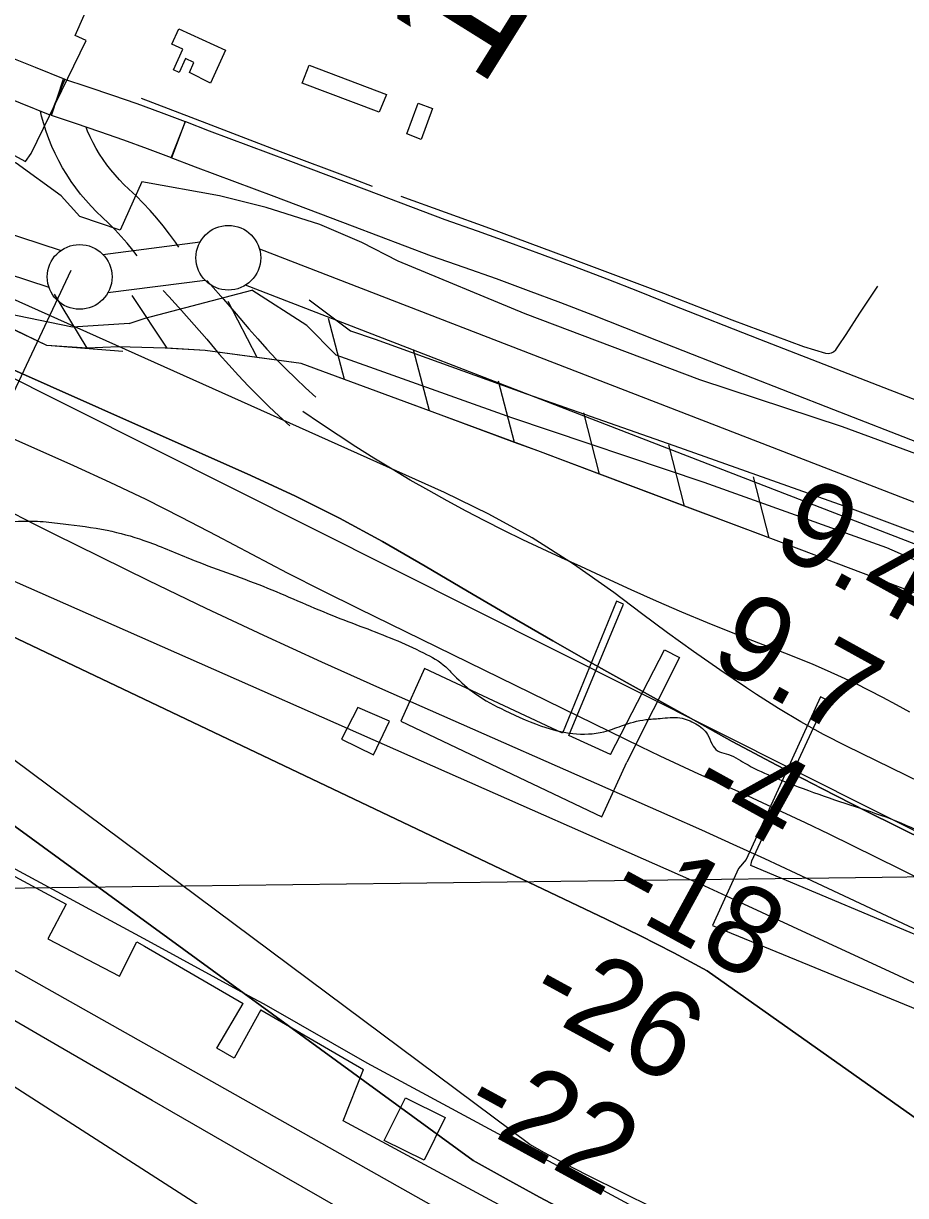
# Model space of a CAD drawing. Extents: x 3734862 to 3772949, y 391520 to 417239.
# Drawn here: x 3739114 to 3739795, y 408738 to 409644 of the extents above; entities that cross this region are included whole.
import ezdxf

# ---------------------------------------------------------------- set-up
doc = ezdxf.new("R2010")
doc.units = 0
for name, color, linetype in [('V-BLDG-OTLN', 7, 'Continuous'), ('V-CHAN-DOCK', 7, 'Continuous'), ('V-FLOD-BASE', 7, 'Continuous'), ('V-GRID-MAJR', 7, 'Continuous'), ('V-LEVE-TOET', 7, 'Continuous'), ('V-RIVR-EDGE', 7, 'Continuous'), ('V-RIVR-RANG', 7, 'Continuous'), ('V-ROAD-CNTR', 7, 'Continuous'), ('V-RRAP-FSHR', 7, 'Continuous'), ('V-SURV-IDEN', 7, 'Continuous'), ('V-SURV-LINE', 7, 'Continuous'), ('V-TOPO-DPTH', 7, 'Continuous'), ('V-TOPO-MAJR', 7, 'Continuous'), ('V-TOPO-MINR', 7, 'Continuous'), ('V-TOPO-SHOR', 7, 'Continuous'), ('V-TOPO-WATR', 7, 'Continuous'), ('V-UTIL-LINE', 7, 'Continuous')]:
    doc.layers.add(name, color=color, linetype=linetype)

msp = doc.modelspace()

# ---------------------------------------------------------------- linework, layer by layer
at = {"layer": 'V-BLDG-OTLN'}
for points in [[(3739258.67, 409597.45), (3739242.48, 409605.83), (3739245.95, 409613.61), (3739239.48, 409616.56), (3739234.59, 409605.83), (3739230.02, 409607.91), (3739237.3, 409623.91), (3739228.79, 409627.78), (3739234.13, 409639.52), (3739270.32, 409623.03)], [(3739389, 409575.07), (3739329.49, 409597.45), (3739334.75, 409611.41), (3739394.62, 409588.88)], [(3739421.27, 409554.1), (3739410.35, 409558.39), (3739419.02, 409582.11), (3739430.02, 409578.09)], [(3739439.88, 408798.78), (3739423.56, 408765.74), (3739392.84, 408780.92), (3739409.16, 408813.95)]]:
    msp.add_lwpolyline(points, close=True, dxfattribs=at)
at = {"layer": 'V-CHAN-DOCK'}
for p, q in [((3738907.07, 409092.08), (3739147.35, 408963.51)), ((3739287.71, 408892.97), (3739300, 408886.37)), ((3739297.46, 408881.72), (3739376.81, 408835.8)), ((3739300, 408886.37), (3739379.49, 408840.81))]:
    msp.add_line(p, q, dxfattribs=at)
for points in [[(3739567.46, 409078.94), (3739535.23, 409093.66), (3739577.5, 409195.17), (3739572.24, 409197.36), (3739530.35, 409095.61), (3739423.83, 409145.47), (3739405.57, 409104.69), (3739560.74, 409030.98), (3739580.19, 409073.13)], [(3739567.46, 409078.94), (3739609.14, 409159.88), (3739620.76, 409153.89), (3739580.19, 409073.13)], [(3739729.53, 409123.49), (3739672.32, 408997.98), (3739666.35, 408991.1), (3739646.26, 408947.08), (3739804.34, 408882.01), (3739826.35, 408930.09), (3739675.76, 408993.34), (3739676.75, 408996.93), (3739734.21, 409121.16), (3739729.53, 409123.49)], [(3739359.8, 409090.79), (3739384.53, 409078.73), (3739396.86, 409104.88), (3739372.49, 409115.27), (3739359.8, 409090.79)], [(3738906.99, 409099.12), (3739210.09, 408935.44), (3739287.71, 408892.97)], [(3739147.35, 408963.51), (3739133.12, 408936.63), (3739188.34, 408907.77), (3739201.91, 408934.31)], [(3739201.91, 408934.31), (3739207.84, 408931.14), (3739283.97, 408886.65)], [(3739297.46, 408881.72), (3739277.1, 408844.51), (3739263.66, 408852.27), (3739283.97, 408886.65)], [(3739379.49, 408840.81), (3739809.65, 408608.64)], [(3739786.75, 408566.78), (3739361.2, 408796.23), (3739376.81, 408835.8)]]:
    msp.add_lwpolyline(points, dxfattribs=at)
at = {"layer": 'V-FLOD-BASE'}
msp.add_lwpolyline([(3739334.78, 409430.31), (3739366.77, 409406.28), (3739385.75, 409399.78), (3739502.67, 409357.65), (3739616.51, 409317.58), (3739752.15, 409269.46), (3739870.6, 409225.01), (3739902.12, 409209.98), (3739957.18, 409174.29), (3740021.39, 409119.55), (3740101.98, 409050.62), (3740182.57, 408982.72), (3740226.59, 408950.42), (3740266.79, 408922.5), (3740306.51, 408904.34), (3740385.75, 408877.53), (3740540.11, 408823.68)], dxfattribs=at)
at = {"layer": 'V-GRID-MAJR'}
msp.add_spline([(3738908.57, 408973.48), (3741556.26, 409006.89), (3746851.64, 409074.29), (3752147, 409142.46), (3757442.36, 409211.39), (3762737.71, 409281.1), (3768033.05, 409351.58), (3770680.71, 409387.1)], degree=3, dxfattribs=at)
at = {"layer": 'V-LEVE-TOET'}
for p, q in [((3739205.63, 409521.46), (3739189.03, 409484.04)), ((3739208.3, 409416.01), (3739290.58, 409437.73)), ((3739333.09, 409410.31), (3739290.58, 409437.73)), ((3739195.96, 409411.96), (3739208.3, 409416.01))]:
    msp.add_line(p, q, dxfattribs=at)
for points in [[(3739195.96, 409411.96), (3739152.29, 409409.07), (3739100.97, 409419.58), (3739059.43, 409433.12), (3738999.95, 409455.99), (3738960.02, 409484.93), (3738928.85, 409522.56), (3738901.33, 409548.9)], [(3739189.03, 409484.04), (3739157.74, 409494.45), (3739143.43, 409510.44), (3739108.62, 409535.76), (3739085.05, 409547.68), (3739050.12, 409548.35)], [(3740557.68, 408873.85), (3740454.07, 408906.67), (3740348.44, 408946.7), (3740299.74, 408966.44), (3740256.21, 408994.88), (3740191.72, 409046.54), (3740108.31, 409115.74), (3740059.72, 409161.16), (3740022.88, 409192.14), (3739990.63, 409216.42), (3739972.71, 409228.83), (3739941.99, 409251.57), (3739902.53, 409271.27), (3739825.63, 409302.94), (3739746.66, 409332.06), (3739636.39, 409368.51), (3739501.54, 409419.46), (3739403.62, 409459.96), (3739375.43, 409474.47), (3739343.14, 409488.48), (3739301.59, 409501.51), (3739265.68, 409510.4), (3739205.63, 409521.46)], [(3739333.09, 409410.31), (3739355.59, 409387.61), (3739490.97, 409339.23), (3739639.7, 409289.26), (3739780.72, 409238.8), (3739854.02, 409206.62)]]:
    msp.add_lwpolyline(points, dxfattribs=at)
at = {"layer": 'V-RIVR-EDGE'}
msp.add_spline([(3738903.54, 409373.09), (3738918.2, 409356.83), (3738938.04, 409332.37), (3738944.77, 409313.81), (3738950.62, 409302.04), (3738968.22, 409286.63), (3738988.99, 409277.53), (3739027.4, 409264.32), (3739054.96, 409258.38), (3739073.5, 409257.43), (3739110.58, 409259.14), (3739127.31, 409259.1), (3739144.94, 409257.25), (3739178.84, 409252.19), (3739207.31, 409244.44), (3739242.54, 409230.33), (3739299.46, 409208.94), (3739352.31, 409186.65), (3739377.15, 409177.1), (3739423.22, 409157.54), (3739440.38, 409146.65), (3739446.69, 409140.3), (3739463.39, 409125.79), (3739485.96, 409113.07), (3739517.58, 409099.88), (3739538.37, 409095.31), (3739562.34, 409096.61), (3739575.91, 409101.09), (3739594.92, 409106.02), (3739605.77, 409106.9), (3739621.14, 409107.31), (3739633.34, 409102.76), (3739642.36, 409094.6), (3739645.96, 409086.9), (3739650.02, 409081.92), (3739656.8, 409079.64), (3739671.25, 409072.37), (3739691.57, 409062.37), (3739712.35, 409054.18), (3739744.42, 409042.8), (3739807.22, 409019.13), (3739846.51, 409003.21), (3739854.2, 409003.19), (3739865.5, 409002.26), (3739871.37, 408996.37), (3739884.9, 408983.22), (3739905.21, 408967.8), (3739923.73, 408960.07), (3739941.35, 408957.31), (3739946.77, 408955.03), (3739950.38, 408950.5), (3739952.16, 408939.2), (3739952.15, 408934.67), (3739958.01, 408927.88), (3739965.69, 408924.69), (3739973.83, 408924.67), (3739980.61, 408926.01), (3739993.27, 408925.53), (3740017.68, 408921.85), (3740043.89, 408913.65), (3740068.28, 408902.74), (3740089.05, 408892.74), (3740121.1, 408870.5), (3740159.47, 408846.44), (3740190.17, 408826.47), (3740216.36, 408811.94), (3740241.65, 408801.02), (3740277.78, 408783.75), (3740307.59, 408770.11), (3740323.41, 408765.55), (3740335.16, 408764.17), (3740368.15, 408757.3), (3740393, 408749.1), (3740424.16, 408733.65), (3740468.87, 408713.19), (3740503.2, 408699.55), (3740521.72, 408692.26), (3740542.48, 408676.84), (3740576.78, 408647.82), (3740600.7, 408631.48), (3740627.79, 408616.94), (3740649.04, 408613.73), (3740673.44, 408606.43), (3740710.94, 408594.58), (3740747.51, 408575.05), (3740787.23, 408546.47), (3740825.6, 408519.69), (3740852.7, 408506.51), (3740900.58, 408488.76)], degree=3, dxfattribs=at)
at = {"layer": 'V-RIVR-RANG'}
msp.add_line((3739150.96, 409452.81), (3738908.98, 408940.41), dxfattribs=at)
at = {"layer": 'V-ROAD-CNTR'}
for points in [[(3739134.86, 409572.84), (3739112.09, 409582.12), (3739089.29, 409591.12), (3739066.4, 409599.88), (3739043.35, 409608.43), (3739053.78, 409636.56), (3739076.98, 409627.96), (3739100.17, 409619.08), (3739123.26, 409609.96), (3739146.18, 409600.62)], [(3739228.6, 409539.87), (3739210.15, 409546.8), (3739191.7, 409553.51), (3739173.18, 409560.02), (3739154.59, 409566.34), (3739135.85, 409572.48), (3739145.19, 409600.99), (3739164.08, 409594.8), (3739182.98, 409588.38), (3739201.8, 409581.76), (3739220.56, 409574.94), (3739239.16, 409567.95)]]:
    msp.add_lwpolyline(points, close=True, dxfattribs=at)
for points in [[(3739202.21, 409464.07), (3739198.75, 409468.56), (3739194.38, 409473.89), (3739189.84, 409479.08), (3739185.12, 409484.14), (3739180.25, 409489.04), (3739175.03, 409493.98), (3739170.76, 409498.05), (3739166.46, 409502.47), (3739162.33, 409507.06), (3739158.39, 409511.79), (3739154.63, 409516.68), (3739151.06, 409521.72), (3739147.69, 409526.88), (3739144.52, 409532.18), (3739141.56, 409537.59), (3739138.81, 409543.11), (3739136.27, 409548.73), (3739133.95, 409554.45), (3739131.85, 409560.25), (3739129.98, 409566.14), (3739128.34, 409572.08), (3739127.45, 409575.86)], [(3739234.15, 409470.86), (3739231.58, 409474.67), (3739227.01, 409481.02), (3739222.24, 409487.23), (3739217.27, 409493.29), (3739212.1, 409499.19), (3739206.75, 409504.93), (3739201.21, 409510.52), (3739195.68, 409515.74), (3739191.86, 409519.38), (3739188.37, 409522.97), (3739185.02, 409526.69), (3739181.82, 409530.54), (3739178.77, 409534.51), (3739175.87, 409538.6), (3739173.13, 409542.79), (3739170.56, 409547.09), (3739168.15, 409551.49), (3739165.91, 409555.98), (3739163.85, 409560.54), (3739162.61, 409563.61)], [(3739808.67, 409318.5), (3739739.98, 409345.27), (3739671.61, 409371.95), (3739603.17, 409398.68), (3739578.47, 409408.65), (3739553.83, 409418.37), (3739529.11, 409427.88), (3739504.32, 409437.2), (3739479.45, 409446.31), (3739454.5, 409455.23), (3739429.23, 409464.03), (3739368.45, 409487.19), (3739307.83, 409510.04), (3739247, 409532.72), (3739228.45, 409539.92), (3739239.31, 409567.89), (3739257.67, 409560.76), (3739318.36, 409538.13), (3739379.09, 409515.24), (3739439.5, 409492.22), (3739464.48, 409483.52), (3739489.66, 409474.52), (3739514.75, 409465.33), (3739539.78, 409455.92), (3739564.72, 409446.32), (3739589.59, 409436.52), (3739614.24, 409426.56), (3739682.52, 409399.89), (3739750.87, 409373.22), (3739818.92, 409346.7)], [(3739255.85, 409445.04), (3739258.65, 409441.97), (3739268.7, 409430.68), (3739278.6, 409419.27), (3739288.19, 409407.91), (3739295.15, 409399.97), (3739302.26, 409392.16), (3739309.52, 409384.48), (3739316.93, 409376.94), (3739324.47, 409369.53), (3739332.16, 409362.26), (3739340.09, 409355.05)], [(3739222.1, 409437.38), (3739226.44, 409432.75), (3739236.37, 409421.88), (3739246.16, 409410.88), (3739255.8, 409399.76), (3739265.45, 409388.35), (3739272.77, 409379.98), (3739280.27, 409371.76), (3739287.91, 409363.67), (3739295.71, 409355.72), (3739303.66, 409347.92), (3739311.76, 409340.27), (3739319.89, 409332.87)], [(3739798.65, 409111.62), (3739788.28, 409117.43), (3739777.81, 409123.07), (3739767.25, 409128.53), (3739756.6, 409133.8), (3739745.85, 409138.89), (3739735.02, 409143.79), (3739724.11, 409148.51), (3739713.11, 409153.04), (3739702.04, 409157.38), (3739682.05, 409164.97), (3739662.15, 409172.79), (3739642.33, 409180.83), (3739622.6, 409189.1), (3739602.97, 409197.58), (3739583.43, 409206.28), (3739564, 409215.2), (3739544.66, 409224.34), (3739529.65, 409230.97), (3739514.73, 409237.8), (3739499.9, 409244.82), (3739485.16, 409252.04), (3739470.52, 409259.45), (3739455.98, 409267.06), (3739441.54, 409274.85), (3739427.2, 409282.84), (3739412.97, 409291.02), (3739398.85, 409299.38), (3739384.85, 409307.93), (3739370.95, 409316.66), (3739357.18, 409325.58), (3739343.52, 409334.68), (3739329.99, 409343.96)]]:
    msp.add_lwpolyline(points, dxfattribs=at)
at = {"layer": 'V-RRAP-FSHR'}
for p, q in [((3739163.48, 409392.85), (3739138.17, 409434.6)), ((3739225.15, 409392.82), (3739198.17, 409433.52)), ((3739294.73, 409385.64), (3739272.33, 409429.03)), ((3739362.2, 409368.65), (3739349.79, 409415.87)), ((3739427.86, 409344.38), (3739415.46, 409391.61)), ((3739493.52, 409320.12), (3739481.12, 409367.35)), ((3739559.08, 409295.58), (3739546.95, 409342.88)), ((3739624.6, 409270.93), (3739612.47, 409318.23)), ((3739690.11, 409246.28), (3739677.98, 409293.58))]:
    msp.add_line(p, q, dxfattribs=at)
for points in [[(3739190.93, 409390.28), (3739132.3, 409394.9), (3738974.21, 409471.33), (3738896.41, 409523.17)], [(3738902.29, 409472.06), (3740332.61, 408753.85), (3741222.95, 408371.28), (3742367.67, 407964.03)], [(3739163.48, 409392.85), (3739132.3, 409394.9), (3739097.42, 409411.77)], [(3739225.15, 409392.78), (3739223.71, 409392.86), (3739187.67, 409393.78), (3739163.48, 409392.85)], [(3741885.29, 408291.44), (3741623.78, 408378.23), (3741440.63, 408438.31), (3741241.33, 408499.82), (3741053.03, 408559.01), (3740880.24, 408628.55), (3740717.65, 408719.54), (3740545.64, 408780.53), (3740315.5, 408858.27), (3740127.64, 408979.39), (3739988.64, 409101.92), (3739872.92, 409177.1), (3739715.19, 409236.85), (3739511.41, 409313.52), (3739328.59, 409381.06), (3739254.6, 409391.06), (3739223.71, 409392.86)], [(3739294.73, 409385.64), (3739254.6, 409391.06), (3739225.15, 409392.78)], [(3739362.2, 409368.65), (3739328.59, 409381.06), (3739294.73, 409385.64)], [(3739427.86, 409344.38), (3739362.2, 409368.65)], [(3739493.52, 409320.12), (3739427.86, 409344.39)], [(3739559.08, 409295.58), (3739511.41, 409313.52), (3739493.52, 409320.12)], [(3739624.6, 409270.93), (3739559.08, 409295.58)], [(3739690.11, 409246.28), (3739624.59, 409270.93)]]:
    msp.add_lwpolyline(points, dxfattribs=at)
at = {"layer": 'V-SURV-LINE'}
for points in [[(3739030.15, 409505.31), (3739143.31, 409468.38)], [(3739134.02, 409439.85), (3739020.86, 409476.78)], [(3739175.57, 409465.34), (3739250.73, 409475.02)], [(3739296.52, 409469.47), (3739908.46, 409232.74)], [(3739254.56, 409445.26), (3739179.41, 409435.59)], [(3739897.63, 409204.77), (3739285.68, 409441.5)]]:
    msp.add_lwpolyline(points, dxfattribs=at)
for centre in [(3739272.47, 409462.69), (3739157.67, 409447.91)]:
    msp.add_circle(centre, 25, dxfattribs=at)
at = {"layer": 'V-TOPO-DPTH'}
for points in [[(3738902.36, 409467.04), (3739289.83, 409294.56), (3739324.24, 409278.48), (3739358.23, 409261.58), (3739391.58, 409243.45), (3739424.5, 409224.5), (3739457.18, 409205.07), (3739489.98, 409185.83), (3739522.93, 409166.88), (3739556, 409148.12), (3739627.36, 409108.05), (3739661.54, 409089.19), (3739695.92, 409070.69), (3739730.57, 409052.73), (3739765.41, 409035.12), (3739980.21, 408928.61), (3740050.93, 408893.45), (3740121.59, 408858.2), (3740192.18, 408822.81), (3740262.72, 408787.32), (3740388.84, 408723.7)], [(3738904.83, 409270.32), (3738926.03, 409259.25), (3738966.34, 409238.49), (3739006.81, 409218.03), (3739047.5, 409198.02), (3739088.34, 409178.31), (3739563.78, 408952.11), (3739590.18, 408939.2), (3739616.37, 408925.9), (3739642.27, 408912.04), (3740278.68, 408461.95), (3741078.1, 408138.95)], [(3738904.83, 409270.32), (3738926.03, 409259.25), (3738966.34, 409238.49), (3739006.81, 409218.03), (3739047.5, 409198.02), (3739088.34, 409178.31), (3739563.78, 408952.11), (3739590.18, 408939.2), (3739616.37, 408925.9), (3739642.27, 408912.04), (3740278.68, 408461.95), (3741078.1, 408138.95)], [(3740354.31, 408678.62), (3740228.47, 408740.64), (3740152.99, 408777.57), (3740077.37, 408814.22), (3740001.54, 408850.43), (3739925.57, 408886.35), (3739710.88, 408987.11), (3739686.64, 408998.38), (3739662.35, 409009.54), (3739637.98, 409020.53), (3739613.56, 409031.41), (3739389.46, 409130.28), (3739344.61, 409150.39), (3739299.92, 409170.85), (3739255.47, 409191.84), (3739211.19, 409213.18), (3739155.14, 409240.6), (3739139.06, 409248.58), (3739123.04, 409256.7), (3739107.12, 409265)], [(3740354.31, 408678.62), (3740228.47, 408740.64), (3740152.99, 408777.57), (3740077.37, 408814.22), (3740001.54, 408850.43), (3739925.57, 408886.35), (3739710.88, 408987.11), (3739686.64, 408998.38), (3739662.35, 409009.54), (3739637.98, 409020.53), (3739613.56, 409031.41), (3739389.46, 409130.28), (3739344.61, 409150.39), (3739299.92, 409170.85), (3739255.47, 409191.84), (3739211.19, 409213.18), (3739155.14, 409240.6), (3739139.06, 409248.58), (3739123.04, 409256.7), (3739107.12, 409265)], [(3740656.38, 408223.23), (3740298.15, 408394.3), (3740276.79, 408404.48), (3740255.41, 408414.64), (3740234.02, 408424.77), (3740212.61, 408434.87), (3739972.95, 408547.81), (3739898.39, 408583.22), (3739823.98, 408618.93), (3739749.79, 408655.1), (3739675.75, 408691.57), (3739551.12, 408753.42), (3739539.56, 408759.29), (3739528.06, 408765.3), (3739516.67, 408771.5), (3739505.35, 408777.84), (3738905.4, 409224.94)], [(3740656.38, 408223.23), (3740298.15, 408394.3), (3740276.79, 408404.48), (3740255.41, 408414.64), (3740234.02, 408424.77), (3740212.61, 408434.87), (3739972.95, 408547.81), (3739898.39, 408583.22), (3739823.98, 408618.93), (3739749.79, 408655.1), (3739675.75, 408691.57), (3739551.12, 408753.42), (3739539.56, 408759.29), (3739528.06, 408765.3), (3739516.67, 408771.5), (3739505.35, 408777.84), (3738905.4, 409224.94)], [(3738906.09, 409170.36), (3739461.56, 408765.51), (3739487.02, 408751.22), (3739512.61, 408737.2), (3739538.43, 408723.59), (3739564.39, 408710.24), (3740234.54, 408372.22), (3740992.73, 408003.78)], [(3738906.09, 409170.36), (3739461.56, 408765.51), (3739487.02, 408751.22), (3739512.61, 408737.2), (3739538.43, 408723.59), (3739564.39, 408710.24), (3740234.54, 408372.22), (3740992.73, 408003.78)]]:
    msp.add_lwpolyline(points, dxfattribs=at)
at = {"layer": 'V-TOPO-MAJR'}
msp.add_lwpolyline([(3740542.56, 408166.19), (3740255.47, 408310.02), (3740234.8, 408320.39), (3740214.14, 408330.76), (3740193.49, 408341.14), (3740172.84, 408351.54), (3739582.64, 408648.9), (3739567.19, 408656.73), (3739551.77, 408664.62), (3739536.39, 408672.59), (3739521.04, 408680.61), (3739493.74, 408694.97), (3739492.06, 408695.86), (3739490.39, 408696.76), (3739488.72, 408697.67), (3739487.05, 408698.58), (3739472.06, 408706.89), (3739462.91, 408711.98), (3739453.77, 408717.07), (3739444.63, 408722.19), (3739435.5, 408727.33), (3738907.92, 409024.76)], dxfattribs=at)
at = {"layer": 'V-TOPO-MINR'}
for points in [[(3739990.83, 408967.47), (3739749.78, 409085.42), (3739731.95, 409094.59), (3739714.38, 409104.21), (3739697.21, 409114.52), (3739680.3, 409125.29), (3739672.42, 409130.52), (3739651.9, 409144.43), (3739631.56, 409158.59), (3739611.47, 409173.12), (3739591.56, 409187.89), (3739570.13, 409204.1), (3739538.97, 409226.04), (3739506.93, 409246.5), (3739473.58, 409264.74), (3739439.36, 409281.5), (3738901.66, 409522.47)], [(3740341.77, 408716.04), (3739791.19, 408990.53), (3739772.93, 408999.57), (3739754.64, 409008.55), (3739736.3, 409017.44), (3739717.94, 409026.26), (3739710.99, 409029.57), (3739696.04, 409036.62), (3739681.05, 409043.58), (3739666, 409050.41), (3739650.91, 409057.15), (3739635.82, 409063.91), (3739620.8, 409070.79), (3739605.85, 409077.85), (3739590.96, 409085.02), (3739373.2, 409191.56), (3739345.62, 409205.26), (3739318.16, 409219.16), (3739290.86, 409233.39), (3739263.68, 409247.84), (3739236.42, 409262.13), (3739208.95, 409276), (3739181.18, 409289.24), (3739153.2, 409302.06), (3738903.03, 409413.25)], [(3740760.53, 408410.41), (3740366.96, 408641.42), (3739657.14, 408969.68), (3739650.46, 408972.75), (3739643.77, 408975.79), (3739637.07, 408978.8), (3739630.35, 408981.78), (3739004.03, 409258.12), (3738991.21, 409263.86), (3738978.45, 409269.7), (3738965.75, 409275.7), (3738953.11, 409281.79), (3738937.1, 409289.63), (3738932.51, 409291.91), (3738927.93, 409294.23), (3738923.38, 409296.6), (3738918.84, 409299.01), (3738914.3, 409301.39), (3738909.72, 409303.7), (3738905.09, 409305.91), (3738904.38, 409306.23)], [(3741078.1, 408138.95), (3740278.68, 408461.95), (3739642.27, 408912.04), (3739616.37, 408925.9), (3739590.18, 408939.2), (3739563.78, 408952.11), (3739088.34, 409178.31), (3739047.5, 409198.02), (3739006.81, 409218.03), (3738966.34, 409238.49), (3738926.03, 409259.25), (3738904.83, 409270.32)], [(3740354.31, 408678.62), (3740228.47, 408740.64), (3740152.99, 408777.57), (3740077.37, 408814.22), (3740001.54, 408850.43), (3739925.57, 408886.35), (3739710.88, 408987.11), (3739686.64, 408998.38), (3739662.35, 409009.54), (3739637.98, 409020.53), (3739613.56, 409031.41), (3739389.46, 409130.28), (3739344.61, 409150.39), (3739299.92, 409170.85), (3739255.47, 409191.84), (3739211.19, 409213.18), (3739155.14, 409240.6), (3739139.06, 409248.58), (3739123.04, 409256.7), (3739107.12, 409265)], [(3740656.38, 408223.23), (3740298.15, 408394.3), (3740276.79, 408404.48), (3740255.41, 408414.64), (3740234.02, 408424.77), (3740212.61, 408434.87), (3739972.95, 408547.81), (3739898.39, 408583.22), (3739823.98, 408618.93), (3739749.79, 408655.1), (3739675.75, 408691.57), (3739551.12, 408753.42), (3739539.56, 408759.29), (3739528.06, 408765.3), (3739516.67, 408771.5), (3739505.35, 408777.84), (3738905.4, 409224.94)], [(3740992.73, 408003.78), (3740234.54, 408372.22), (3739564.39, 408710.24), (3739538.43, 408723.59), (3739512.61, 408737.2), (3739487.02, 408751.22), (3739461.56, 408765.51), (3738906.09, 409170.36)], [(3739287.9, 408706.37), (3738942.65, 408927.82)], [(3739435.81, 408684.23), (3739299.83, 408762.2), (3739213.79, 408811.72), (3739127.87, 408861.45), (3739042.12, 408911.48)]]:
    msp.add_lwpolyline(points, dxfattribs=at)
at = {"layer": 'V-TOPO-SHOR'}
for points in [[(3739205.08, 409586.02), (3739255.55, 409566.57), (3739312.59, 409544.78), (3739368.73, 409523.76), (3739383.53, 409517.89)], [(3739405.55, 409510.18), (3739474.19, 409485.5), (3739534.44, 409463.04), (3739608.48, 409435.24), (3739661.27, 409414.75), (3739716.63, 409394.12), (3739733.5, 409389.02), (3739735.57, 409388.88), (3739738.02, 409389.26), (3739739.7, 409390.02), (3739741.38, 409391.69), (3739743.46, 409394.65), (3739749.56, 409403.52), (3739759.95, 409419.98), (3739773.98, 409440.81)]]:
    msp.add_lwpolyline(points, dxfattribs=at)
at = {"layer": 'V-TOPO-WATR'}
msp.add_lwpolyline([(3740388.84, 408723.7), (3740262.72, 408787.32), (3740192.18, 408822.81), (3740121.59, 408858.2), (3740050.93, 408893.45), (3739980.21, 408928.61), (3739765.41, 409035.12), (3739730.57, 409052.73), (3739695.92, 409070.69), (3739661.54, 409089.19), (3739627.36, 409108.05), (3739556, 409148.12), (3739522.93, 409166.88), (3739489.98, 409185.83), (3739457.18, 409205.07), (3739424.5, 409224.5), (3739391.58, 409243.45), (3739358.23, 409261.58), (3739324.24, 409278.48), (3739289.83, 409294.56), (3738902.36, 409467.04)], dxfattribs=at)
at = {"layer": 'V-UTIL-LINE'}
msp.add_lwpolyline([(3739059.86, 409463.9), (3739086.59, 409502.65), (3739106.78, 409541.81), (3739115.99, 409537.15), (3739120.25, 409543.29), (3739162.59, 409630.45), (3739154.14, 409634.33), (3739161.14, 409650.08), (3739196.91, 409739.55)], dxfattribs=at)

# ---------------------------------------------------------------- texts
at = {"layer": 'V-RIVR-RANG'}
for s, rotation, p in [('9.4', 331.05833, (3739690.23, 409237.91)), ('9.7', 331.05833, (3739642.06, 409150.28)), ('-4', 331.05833, (3739625.74, 409045.03)), ('-18', 331.34533, (3739563.48, 408964.81)), ('-26', 331.34533, (3739500.96, 408885.02)), ('-22', 331.34533, (3739450.48, 408798.65))]:
    msp.add_text(s, height=67, rotation=rotation, dxfattribs=at).set_placement(p)
at = {"layer": 'V-SURV-IDEN'}
msp.add_text('1358+35.3', height=100, rotation=58.00477, dxfattribs=at).set_placement((3739467.26, 409592.04))

doc.saveas('drawing.dxf')
